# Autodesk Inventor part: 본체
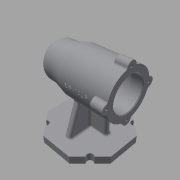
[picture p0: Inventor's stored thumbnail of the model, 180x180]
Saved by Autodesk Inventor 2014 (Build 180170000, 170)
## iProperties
Created: 2021-01
Part Number: 본체
Material: Generic
Document SubType Name: Modeling
Designer: kh
Density: 1 g/cm^3
Appearance: Default
Author: kh
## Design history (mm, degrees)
sketch "Sketch1" dims "d0" = 100
  geometry: L1 (50, 20.711)-(50, -20.711); L2 (20.711, -50)-(-20.711, -50); L3 (-50, -20.711)-(-50, 20.711); L4 (-20.711, 50)-(20.711, 50); L5 (35.355, 35.355)-(-35.355, -35.355); L6 (-35.355, 35.355)-(35.355, -35.355); L7 (-50, 0)-(50, 0); L8 (0, 50)-(0, -50); L9 (-50, 20.711)-(-38.537, 32.173); L10 (-32.173, 38.537)-(-20.711, 50); L11 (-20.711, -50)-(-32.173, -38.537); L12 (-38.537, -32.173)-(-50, -20.711); L13 (50, -20.711)-(38.537, -32.173); L14 (32.173, -38.537)-(20.711, -50); L15 (20.711, 50)-(32.173, 38.537); L16 (38.537, 32.173)-(50, 20.711); A1 r 4.5 centre (-35.355, -35.355) between (-32.173, -38.537) and (-38.537, -32.173); A2 r 4.5 centre (35.355, -35.355) between (38.537, -32.173) and (32.173, -38.537); A3 r 4.5 centre (-35.355, 35.355) between (-38.537, 32.173) and (-32.173, 38.537); A4 r 4.5 centre (35.355, 35.355) between (32.173, 38.537) and (38.537, 32.173); 4 further points
  constraints: 32 end point, 8 point on circle, 6 coincident, 6 midpoint, 4 centre point, 1 vertical alignment, 11 other
  dimensions: "d1" = 9 diameter of A1; "d2" = 9 diameter of A2; "d3" = 9 diameter of A3; "d4" = 9 diameter of A4; "d6" = 50 distance between parallel lines of L1 L8 (derived); "d7" = 45 deg angle of L6 L7
extrude "Extrusion1" new body sketch "Sketch1" distance "d8" = 10; taper "d9" = 0 deg
sketch "Sketch2"
  geometry: L1 (0, 0)-(0, 75); L2 (65.016, 75)-(-65.016, 75); L3 (-50, 75)-(-50, 105); L4 (-50, 105)-(10, 105); L5 (10, 105)-(30, 100); L6 (30, 100)-(50, 100); L7 (50, 100)-(50, 75); L8 (-50, 0)-(-50, 10) reference; L9 (-50, 96)-(-35, 96); L10 (-35, 96)-(-35, 99); L11 (-35, 99)-(7, 99); L12 (7, 99)-(7, 96); L13 (7, 96)-(19, 96); L14 (19, 96)-(19, 92.5); L15 (19, 92.5)-(37, 92.5); L16 (37, 92.5)-(37, 91); L17 (37, 91)-(41, 91); L18 (41, 91)-(41, 85.5); L19 (41, 85.5)-(44, 85.5); L20 (44, 85.5)-(44, 75)
  constraints: 38 end point, 9 parallel, 7 perpendicular, 4 point on line, 2 collinear, 1 midpoint, 1 vertical
  dimensions: "d10" = 75 distance of L1.end L1.start; "d11" = 60 diameter of L4 L2; "d12" = 50 diameter of L6 L2; "d13" = 100 distance between parallel lines of L7 L3; "d14" = 20 distance from line of L7 L5.end; "d15" = 40 distance from line of L7 L4.end; "d16" = 42 diameter of L9 L2; "d17" = 48 diameter of L11 L2; "d18" = 42 diameter of L13 L2; "d19" = 35 diameter of L15 L2; "d20" = 32 diameter of L17 L2; "d21" = 21 diameter of L19 L2; "d22" = 15 distance between parallel lines of L3 L10; "d28" = 42 distance between parallel lines of L12 L10; "d31" = 3 distance between parallel lines of L20 L18; "d32" = 12 distance between parallel lines of L12 L14; "d33" = 18 distance between parallel lines of L16 L14; "d34" = 4 distance between parallel lines of L16 L18
revolve "Revolution1" sketch "Sketch2" stored, may be unused: angle "d35" = 90 deg
sketch "Sketch3"
  geometry: L1 (32.173, 10)-(20.711, 10) reference; L2 (30.855, 10)-(38.537, 10) reference; L3 (50, 10)-(38.537, 10) reference; L4 (-50, 45)-(10, 45) reference; L5 (10, 45)-(30, 50) reference; L6 (27, 10)-(19.724, 47.431); L7 (50, 0)-(50, 10) reference; L8 (-27, 45)-(-27, 10); L9 (-50, 0)-(-50, 10) reference; 1 further point
  constraints: 4 end point, 3 point on line, 1 parallel
  dimensions: "d36" = 101 deg angle of L2 L6; "d37" = 23 distance from line of L7 L6.start; "d38" = 23 distance between parallel lines of L9 L8
feature "Rib1" dims "d39" = 1, "d40" = 8, "d41" = 0, "d42" = 0, "d43" = 1, "d44" = 1
feature "Rib2" dims "d45" = 1, "d46" = 8, "d47" = 0, "d48" = 0, "d49" = 1, "d50" = 1
sketch "Sketch4"
  geometry: L1 (30.855, 10)-(38.537, 10) reference; L2 (20.711, 10)-(32.173, 10) reference; L3 (-32.173, 10)-(-20.711, 10) reference; L4 (-38.537, 10)-(-30.855, 10) reference; L5 (-35, 10)-(-19.606, 52.293); L6 (35, 10)-(19.606, 52.293); L7 (-50, 0)-(-50, 10) reference; L8 (50, 0)-(50, 10) reference; A1 r 30 centre (0, 75) between (-19.606, 52.293) and (19.606, 52.293) reference; 1 further point
  constraints: 4 end point, 2 point on circle, 2 point on line
  dimensions: "d51" = 110 deg angle of L1 L6; "d52" = 110 deg angle of L4 L5; "d53" = 15 distance from line of L7 L5.start; "d54" = 15 distance from line of L6.start L8
feature "Rib3" dims "d55" = 1, "d56" = 8, "d57" = 0, "d58" = 0, "d59" = 1, "d60" = 1
feature "Rib4" dims "d61" = 1, "d62" = 8, "d63" = 0, "d64" = 0, "d65" = 1, "d66" = 1
sketch "Sketch5"
  geometry: L1 (-30, 0)-(30, 0); L2 (0, -30)-(0, 30); C1 r 6 at (-30, 0); C2 r 6 at (0, 30); C3 r 6 at (30, 0); C4 r 6 at (0, -30); A1 r 30 centre (0, 0) between (-30, 0) and (30, 0) reference; 3 further points
  constraints: 4 centre point, 4 coincident, 4 end point, 4 midpoint, 4 point on circle, 1 horizontal, 1 perpendicular
  dimensions: "d67" = 12 diameter of C1; "d68" = 12 diameter of C2; "d69" = 12 diameter of C3; "d70" = 12 diameter of C4
extrude "Extrusion2" join sketch "Sketch5" distance "d71" = 16; taper "d72" = 0 deg
sketch "Sketch6"
  geometry: A1 r 6 centre (0, 0) between (0.6, 5.97) and (0.6, -5.97) reference; A2 r 6 centre (30, -30) between (24.03, -29.4) and (35.97, -29.4) reference; A3 r 6 centre (60, 0) between (59.4, -5.97) and (59.4, 5.97) reference; A4 r 6 centre (30, 30) between (35.97, 29.4) and (24.03, 29.4) reference; 5 further points
  constraints: 4 coincident
hole "Hole1" sketch "Sketch6" at (0, 0), (30, -30), (60, 0), (30, 30) diameter "d73" = 3.242; stored, may be unused: countersink angle "d77" = 90 deg, drill point angle "d79" = 118 deg; dims "d74" = 8, "d75" = 4, "d76" = 2, "d78" = 10
workplane "Work Plane1"
sketch "Sketch7"
  geometry: L1 (-5.162, 79.27)-(29.162, 79.27); L2 (29.162, 79.27)-(29.162, 70.73); L3 (29.162, 70.73)-(-5.162, 70.73); L4 (-5.162, 70.73)-(-5.162, 79.27); L5 (-5.162, 79.27)-(29.162, 70.73); L6 (50, 96)-(50, 54) reference; L7 (-50, 100)-(-50, 50) reference; L8 (50, 75)-(-50, 75); 2 further points
  constraints: 4 end point, 3 midpoint, 1 point on line, 2 other
  dimensions: "d81" = 38 distance from line of L6 point (12, 75)
emboss "Emboss1" sketch "Sketch7" dims "d82" = 0.5, "d83" = 0
fillet "Fillet1" dims "d84" = 3
fillet "Fillet2" dims "d85" = 3
fillet "Fillet3" dims "d86" = 3
fillet "Fillet4" dims "d87" = 0.3
fillet "Fillet5" dims "d88" = 3
chamfer "Chamfer1" distance "d89" = 1; stored, may be unused: second distance "d90" = 2, angle "d91" = 45 deg
fillet "Fillet6" dims "d92" = 10
fillet "Fillet7" dims "d93" = 3
fillet "Fillet8" dims "d94" = 1
fillet "Fillet9" dims "d95" = 3
fillet "Fillet10" dims "d96" = 1
fillet "Fillet11" dims "d97" = 3
body "Solid1"
